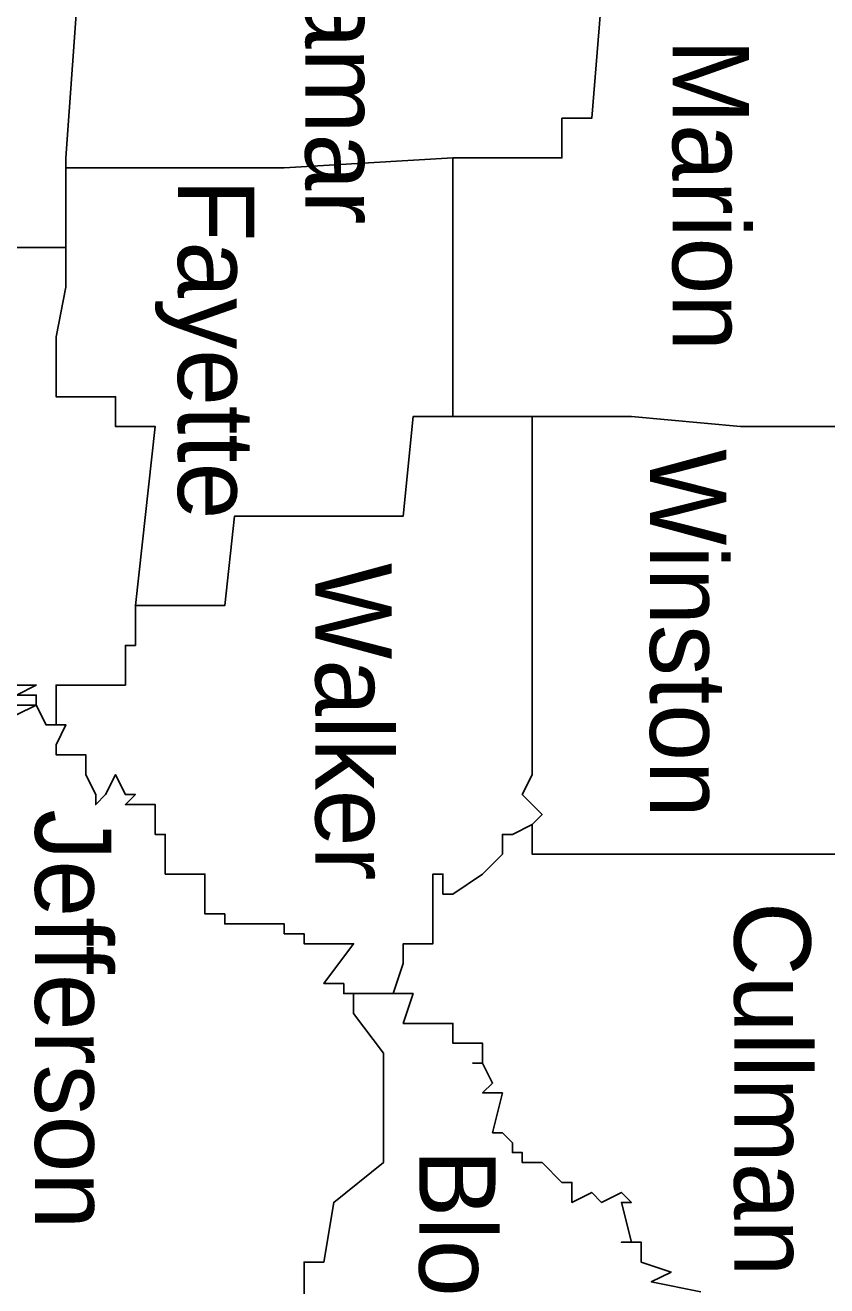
# Model space of a CAD drawing. Extents: x 0 to 0.917, y 0 to 0.708.
# Drawn here: x 0.5269 to 0.5816, y 0.5269 to 0.6129 of the extents above; entities that cross this region are included whole.
import ezdxf

# ---------------------------------------------------------------- set-up
doc = ezdxf.new("R2010")
doc.units = 0
doc.layers.add('ANNO-SHT', color=7, linetype='Continuous')
doc.layers.add('ANNO-TXT', color=7, linetype='Continuous')

msp = doc.modelspace()

# ---------------------------------------------------------------- linework, layer by layer
at = {"layer": 'ANNO-SHT'}
for points in [[(0.52966, 0.603197), (0.52966, 0.603876), (0.531013, 0.62288)], [(0.5662, 0.618129), (0.5662, 0.614735), (0.565523, 0.60659), (0.563493, 0.60659), (0.563493, 0.603876), (0.558756, 0.603876), (0.55605, 0.603876), (0.55605, 0.601161), (0.55605, 0.595731), (0.55605, 0.592337), (0.55605, 0.586229)], [(0.5662, 0.618129), (0.5662, 0.614735), (0.565523, 0.60659), (0.563493, 0.60659), (0.563493, 0.603876), (0.558756, 0.603876), (0.55605, 0.603876), (0.55605, 0.601161), (0.55605, 0.595731), (0.55605, 0.592337), (0.55605, 0.586229)], [(0.52966, 0.603197), (0.536427, 0.603197), (0.539133, 0.603197), (0.544547, 0.603197), (0.55605, 0.603876)], [(0.52966, 0.603197), (0.52966, 0.601161), (0.52966, 0.597767), (0.51342, 0.597767)], [(0.534397, 0.573333), (0.53575, 0.58555), (0.533043, 0.58555), (0.533043, 0.586908), (0.533043, 0.587586), (0.528983, 0.587586), (0.528983, 0.591659), (0.52966, 0.595052), (0.52966, 0.597767)], [(0.55605, 0.586229), (0.553343, 0.586229), (0.553343, 0.586229), (0.552666, 0.579442), (0.54793, 0.579442), (0.541163, 0.579442), (0.541163, 0.579442), (0.540487, 0.573333), (0.534397, 0.573333), (0.534397, 0.571297), (0.534397, 0.570618), (0.53372, 0.570618), (0.53372, 0.567904), (0.528983, 0.567904), (0.528983, 0.565189)], [(0.55605, 0.586229), (0.557403, 0.586229), (0.561463, 0.586229)], [(0.55605, 0.586229), (0.557403, 0.586229), (0.561463, 0.586229)], [(0.55605, 0.586229), (0.557403, 0.586229), (0.561463, 0.586229)], [(0.561463, 0.586229), (0.561463, 0.582835), (0.561463, 0.577406), (0.561463, 0.570618), (0.561463, 0.562474), (0.561463, 0.561795), (0.560786, 0.560438), (0.561463, 0.559759), (0.56214, 0.55908), (0.561463, 0.558401)], [(0.561463, 0.586229), (0.561463, 0.582835), (0.561463, 0.577406), (0.561463, 0.570618), (0.561463, 0.562474), (0.561463, 0.561795), (0.560786, 0.560438), (0.561463, 0.559759), (0.56214, 0.55908), (0.561463, 0.558401)], [(0.561463, 0.586229), (0.56823, 0.586229), (0.575673, 0.58555), (0.577703, 0.58555), (0.583116, 0.58555)], [(0.526277, 0.566546), (0.52763, 0.566546), (0.52763, 0.567225), (0.526277, 0.567225), (0.52763, 0.567904), (0.52763, 0.567904), (0.52763, 0.567904), (0.526277, 0.567904)], [(0.528983, 0.565189), (0.528307, 0.565189), (0.52763, 0.566546), (0.526277, 0.565867)], [(0.528983, 0.565189), (0.528983, 0.565189), (0.52966, 0.565189), (0.52966, 0.565189), (0.528983, 0.563831), (0.528983, 0.563831), (0.528983, 0.563152), (0.528983, 0.563152), (0.52966, 0.563152), (0.531013, 0.563152), (0.531013, 0.562474), (0.531013, 0.561795), (0.531013, 0.561795), (0.53169, 0.560438), (0.53169, 0.559759), (0.532367, 0.560438), (0.533043, 0.561795), (0.53372, 0.560438), (0.534397, 0.560438), (0.53372, 0.559759), (0.53575, 0.559759), (0.53575, 0.558401), (0.53575, 0.557723), (0.536427, 0.557723), (0.536427, 0.555008), (0.539133, 0.555008), (0.539133, 0.552293), (0.540487, 0.552293), (0.540487, 0.551614), (0.54387, 0.551614), (0.54387, 0.551614), (0.544547, 0.551614), (0.544547, 0.550936), (0.5459, 0.550936), (0.5459, 0.550257), (0.549283, 0.550257), (0.547253, 0.547542), (0.548606, 0.547542), (0.548606, 0.546863), (0.549283, 0.546863)], [(0.561463, 0.558401), (0.56011, 0.557723), (0.559433, 0.557723), (0.559433, 0.556365), (0.55808, 0.555008), (0.55605, 0.55365), (0.555373, 0.55365), (0.555373, 0.555008), (0.554696, 0.555008), (0.554696, 0.555008), (0.554696, 0.550257), (0.552666, 0.550257), (0.552666, 0.549578), (0.552666, 0.549578), (0.552666, 0.548899), (0.55199, 0.546863)], [(0.58244, 0.556365), (0.57432, 0.556365), (0.561463, 0.556365), (0.561463, 0.558401)], [(0.5459, 0.525823), (0.5459, 0.528538), (0.5459, 0.528538), (0.5459, 0.528538), (0.5459, 0.528538), (0.5459, 0.528538), (0.547253, 0.528538), (0.547253, 0.528538), (0.54793, 0.53261), (0.551313, 0.535325), (0.551313, 0.53804), (0.551313, 0.540076), (0.551313, 0.542791), (0.549283, 0.545506), (0.549283, 0.546863)], [(0.549283, 0.546863), (0.551313, 0.546863), (0.551313, 0.546863), (0.55199, 0.546863)], [(0.55199, 0.546863), (0.55199, 0.546863), (0.552666, 0.546863), (0.553343, 0.546863), (0.552666, 0.544827), (0.553343, 0.544827), (0.553343, 0.544827), (0.554696, 0.544827), (0.555373, 0.544827), (0.55605, 0.544827), (0.55605, 0.544148), (0.55605, 0.54347), (0.55808, 0.54347), (0.55808, 0.542112), (0.557403, 0.542112), (0.55808, 0.542112), (0.558756, 0.540755), (0.55808, 0.540076), (0.559433, 0.540076), (0.558756, 0.537361), (0.559433, 0.537361), (0.56011, 0.536682), (0.56011, 0.536682), (0.56011, 0.536682), (0.56011, 0.536004), (0.560786, 0.536004), (0.560786, 0.535325), (0.561463, 0.535325), (0.561463, 0.535325), (0.561463, 0.535325), (0.56214, 0.535325), (0.563493, 0.533968), (0.56417, 0.533968), (0.56417, 0.533289), (0.56417, 0.53261), (0.565523, 0.533289), (0.5662, 0.53261), (0.5662, 0.53261), (0.567553, 0.533289), (0.56823, 0.53261), (0.567553, 0.53261), (0.56823, 0.529895), (0.567553, 0.529895), (0.568906, 0.529895), (0.568906, 0.528538), (0.570936, 0.527859), (0.569583, 0.52718), (0.569583, 0.52718), (0.572966, 0.526502)]]:
    msp.add_lwpolyline(points, dxfattribs=at)

# ---------------------------------------------------------------- texts
at = {"layer": 'ANNO-TXT'}
for s, p in [('Lamar', (0.545988, 0.61909)), ('Marion', (0.57104, 0.61199)), ('Fayette', (0.537301, 0.602439)), ('Winston', (0.569507, 0.584014)), ('Walker', (0.54668, 0.576242)), ('Jefferson', (0.527557, 0.559432)), ('Cullman', (0.575246, 0.55311)), ('Blount', (0.553758, 0.536244))]:
    msp.add_text(s, height=0.0052083, rotation=270, dxfattribs=at).set_placement(p)

doc.saveas('drawing.dxf')
